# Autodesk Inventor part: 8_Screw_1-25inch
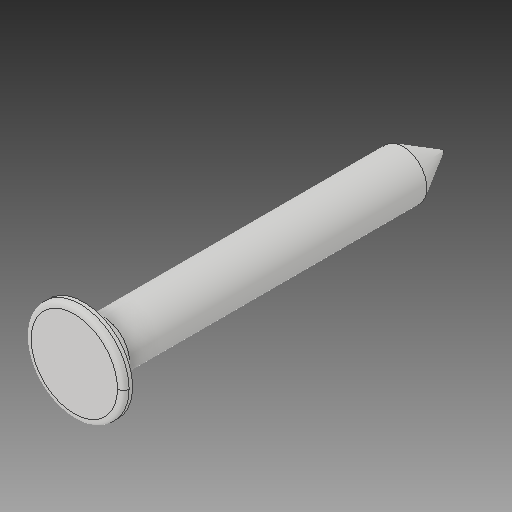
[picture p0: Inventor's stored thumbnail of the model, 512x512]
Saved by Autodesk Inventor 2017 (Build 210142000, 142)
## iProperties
Created: 2017-05
Part Number: 8_Screw_1-25inch
Material: Generic
Document SubType Name: Modeling
Designer: Savy
Density: 1 g/cm^3
Appearance: Default
Mass: 0.469579 g
Surface Area: 4.9238 cm^2
Volume: 0.469579 cm^3
Author: Savy
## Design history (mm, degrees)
feature "SOLID1"
body "Solid1"
